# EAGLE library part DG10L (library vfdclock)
Early Vacuum Florescent Tube made by ISE denshi. It had unique font with 8 segments. Looks like hand-written number. Official specs are unknown but filament supply is about 0.6V/30mA
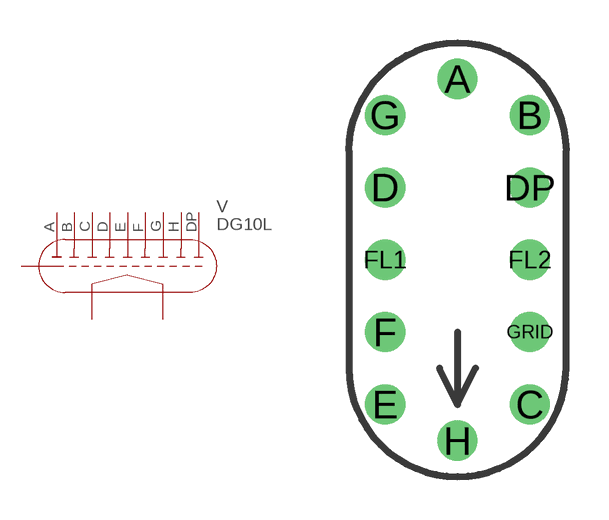
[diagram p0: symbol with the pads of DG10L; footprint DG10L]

Designator prefix V

## DG10L  [DG10L]
A  A  in
B  B  in
C  C  in
D  D  in
DP  DP  in
E  E  in
F  F  in
FL1  FL1  sup
FL2  FL2  sup
G  G  in
GRID  GRID  in
H  H  in

## Footprint DG10L (pad centres in mm)
drill 0.9 round: A 0,6.35; B 2.54,5.08; C 2.54,-5.08; D -2.54,2.54; DP 2.54,2.54; E -2.54,-5.08; F -2.54,-2.54; FL1 -2.54,0; FL2 2.54,0; G -2.54,5.08; GRID 2.54,-2.54; H 0,-6.35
